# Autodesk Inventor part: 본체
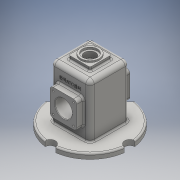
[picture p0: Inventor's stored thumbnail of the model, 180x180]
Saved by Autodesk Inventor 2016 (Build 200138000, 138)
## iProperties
Created: 2018-07
Part Number: 본체
Material: 일반
Document SubType Name: Modeling
Designer: 2-PC07
Density: 1 g/cm^3
Appearance: 기본값
Author: 2-PC07
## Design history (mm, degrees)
sketch "스케치1"
  geometry: C1 r 75 at (0, 0); 1 further point
  constraints: 1 centre point, 1 coincident
  dimensions: "d0" = 150 diameter of C1
extrude "돌출1" new body sketch "스케치1" distance "d1" = 10; taper "d2" = 0 deg
sketch "스케치2"
  geometry: L1 (-37, -37)-(37, -37); L2 (37, -37)-(37, 37); L3 (37, 37)-(-37, 37); L4 (-37, 37)-(-37, -37); L5 (-37, -37)-(37, 37); L6 (37, -37)-(-37, 37); 1 further point
  constraints: 12 end point, 2 midpoint, 2 parallel, 1 horizontal, 1 perpendicular
  dimensions: "d3" = 74 distance of L3.end L2.end; "d4" = 74 distance of L1.end L2.end
extrude "돌출2" join sketch "스케치2" distance "d5" = 100; taper "d6" = 0 deg
sketch "스케치3"
  geometry: L1 (-20, -20)-(20, -20); L2 (20, -20)-(20, 20); L3 (20, 20)-(-20, 20); L4 (-20, 20)-(-20, -20); L5 (-20, -20)-(20, 20); L6 (20, -20)-(-20, 20); 1 further point
  constraints: 12 end point, 2 midpoint, 2 parallel, 1 horizontal, 1 perpendicular
  dimensions: "d7" = 40 distance of L3.end L2.end; "d8" = 40 distance of L2.end L1.end
extrude "돌출3" join sketch "스케치3" distance "d9" = 7; taper "d10" = 0 deg
sketch "스케치4"
  geometry: C1 r 17.5 at (0, 0); 1 further point
  constraints: 1 centre point, 1 coincident
  dimensions: "d11" = 35 diameter of C1
extrude "돌출4" join sketch "스케치4" distance "d12" = 3; taper "d13" = 0 deg
sketch "스케치5"
  geometry: L1 (32, -32)-(-32, -32); L2 (-32, -32)-(-32, 32); L3 (-32, 32)-(32, 32); L4 (32, 32)-(32, -32); L5 (32, -32)-(-32, 32); L6 (-32, -32)-(32, 32); 1 further point
  constraints: 12 end point, 2 midpoint, 2 parallel, 1 horizontal, 1 perpendicular
  dimensions: "d14" = 64 distance of L2.end L3.end; "d15" = 64 distance of L1.end L2.end
extrude "돌출5" cut sketch "스케치5" distance "d16" = 105; taper "d17" = 0 deg
sketch "스케치6"
  geometry: L1 (74, 0)-(0, 0) reference; L2 (74, 0)-(74, 100) reference; L3 (0, 100)-(74, 100) reference; L4 (0, 0)-(0, 100) reference; L5 (12, 20)-(62, 20); L6 (62, 20)-(62, 70); L7 (62, 70)-(12, 70); L8 (12, 70)-(12, 20); L9 (12, 20)-(62, 70); L10 (62, 20)-(12, 70); L11 (5, -10)-(69, -10) reference; 2 further points
  constraints: 12 end point, 2 midpoint, 2 parallel, 1 horizontal, 1 perpendicular
  dimensions: "d18" = 50 distance of L7.end L6.end; "d19" = 50 distance of L6.end L5.end; "d20" = 55 distance of point (37, -10) point (37, 45); "d21" = 37 distance from line of point (37, 45) L2
extrude "돌출6" join sketch "스케치6" distance "d22" = 13; taper "d23" = 0 deg
sketch "스케치7"
  geometry: L1 (-32, 0)-(-32, 105) reference; L2 (-32, 80)-(-25, 77.452); L3 (-25, 77.452)-(-25, 55); L4 (-37, 80)-(-50, 80) reference; L5 (-25, 55)-(-32, 55); L6 (-32, 80)-(-32, 55); L7 (-50, 80)-(-50, 30) reference; 2 further points
  constraints: 8 end point, 3 point on line, 2 perpendicular, 1 collinear, 1 midpoint
  dimensions: "d24" = 7 horizontal distance of L2.start L2.end; "d25" = 50 diameter of L2.start L5; "d26" = 110 deg angle of L1 L2
revolve "회전1" sketch "스케치7" stored, may be unused: angle "d27" = 90 deg
sketch "스케치8"
  geometry: C1 r 10 at (-75, 0); C2 r 10 at (0, 75); C3 r 10 at (75, 0); C4 r 10 at (0, -75); A1 r 75 centre (0, 0) between (-75, 0) and (0, 75) reference; A2 r 75 centre (0, 0) between (0, 75) and (75, 0) reference; 1 further point
  constraints: 7 point on circle, 4 centre point, 3 equal radius, 2 horizontal alignment, 2 vertical alignment
  dimensions: "d29" = 10 radius of C1
extrude "돌출7" cut sketch "스케치8" stored distance "d30" = 13; taper "d31" = 0 deg
sketch "스케치9"
  geometry: L1 (74, 0)-(74, 100) reference; C1 r 16 at (37, 45); 1 further point
  constraints: 1 centre point
  dimensions: "d32" = 32 diameter of C1; "d33" = 37 distance from line of L1 C1.centre; "d34" = 55 distance of point (37, -10) C1.centre
extrude "돌출8" cut sketch "스케치9" stored distance "d35" = 13; taper "d36" = 0 deg
hole "구멍1" diameter "d39" = 21; stored, may be unused: countersink angle "d43" = 90 deg, drill point angle "d45" = 118 deg; dims "d37" = 10, "d38" = 10, "d40" = 6, "d41" = 28, "d42" = 4, "d44" = 8
sketch "스케치10"
  geometry: L1 (62, 70)-(12, 70) reference; L2 (12, 70)-(12, 20) reference; L3 (12, 20)-(62, 20) reference; L4 (62, 20)-(62, 70) reference; 5 further points
  constraints: 2 horizontal alignment, 2 vertical alignment
  dimensions: "d46" = 6 distance from line of L1 point (18, 64); "d47" = 6 distance from line of L2 point (18, 64); "d48" = 6 distance from line of L3 point (18, 26); "d49" = 6 distance from line of L4 point (56, 26)
hole "구멍2" sketch "스케치10" at (18, 64), (18, 26), (56, 26), (56, 64) diameter "d50" = 3.242; stored, may be unused: countersink angle "d54" = 90 deg, drill point angle "d56" = 118 deg; dims "d51" = 8, "d52" = 28, "d53" = 4, "d55" = 10
fillet "모깎기1" dims "d57" = 8
fillet "모깎기2" dims "d58" = 3, "d59" = 6
fillet "모깎기3" dims "d60" = 3, "d61" = 3
fillet "모깎기4" dims "d62" = 3
fillet "모깎기5" dims "d72" = 3
chamfer "모따기1" distance "d63" = 1; stored, may be unused: second distance "d64" = 2, angle "d65" = 45 deg
sketch "스케치11"
  geometry: L1 (8, 83.5)-(50, 83.5); L2 (50, 83.5)-(50, 76.5); L3 (50, 76.5)-(8, 76.5); L4 (8, 76.5)-(8, 83.5); L5 (8, 80)-(50, 80); L6 (29, 83.5)-(29, 76.5); L7 (66, 0)-(66, 92) reference; L8 (46.5, 110)-(11.5, 110) reference; 1 further point
  constraints: 4 end point, 4 midpoint, 2 other
  dimensions: "d66" = 7 distance of L1.end L2.end; "d67" = 42 distance of L1.start L1.end; "d68" = 37 distance between parallel lines of L7 L6; "d69" = 30 distance between parallel lines of L5 L8
feature "엠보싱1" sketch "스케치11" dims "d70" = 0.5, "d71" = 0
node "솔리드1"
mirror "대칭1"
mirror "대칭2"
mirror "대칭3"
node "투영된 루프1"
